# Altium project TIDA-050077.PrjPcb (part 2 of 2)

## Sheet TIDA-050077_HKeeping.SchDoc
size 431 x 279 mm; Date: Not shown in title block; ApprovedBy: Not shown in title block; CheckedBy: Not shown in title block; Author: Not shown in title block; CompanyName: Not shown in title block; Engineer: Not shown in title block; Organization: Not shown in title block; Address1: Not shown in title block; Address2: Not shown in title block; Address3: Not shown in title block; Address4: Not shown in title block; DocumentNumber: 6; Revision: Use project parameter SCH_Rev; SheetNumber: 4; SheetTotal: 5; PageSetup: Record=PageOptions¦CenterHorizontal=True¦CenterVertical=True¦PrintScale=1.00¦XCorrection=1.00¦YCorrection=1.00¦PrintKind=0¦BorderSize=5000000¦LeftOffset=0¦BottomOffset=0¦Orientation=2¦PaperLength=1000¦PaperWidth=1000¦Scale=100¦PaperSource=15¦PrintQuality=600¦MediaType=1¦DitherType=10¦PaperKind=Letter¦PrintScaleMode=1
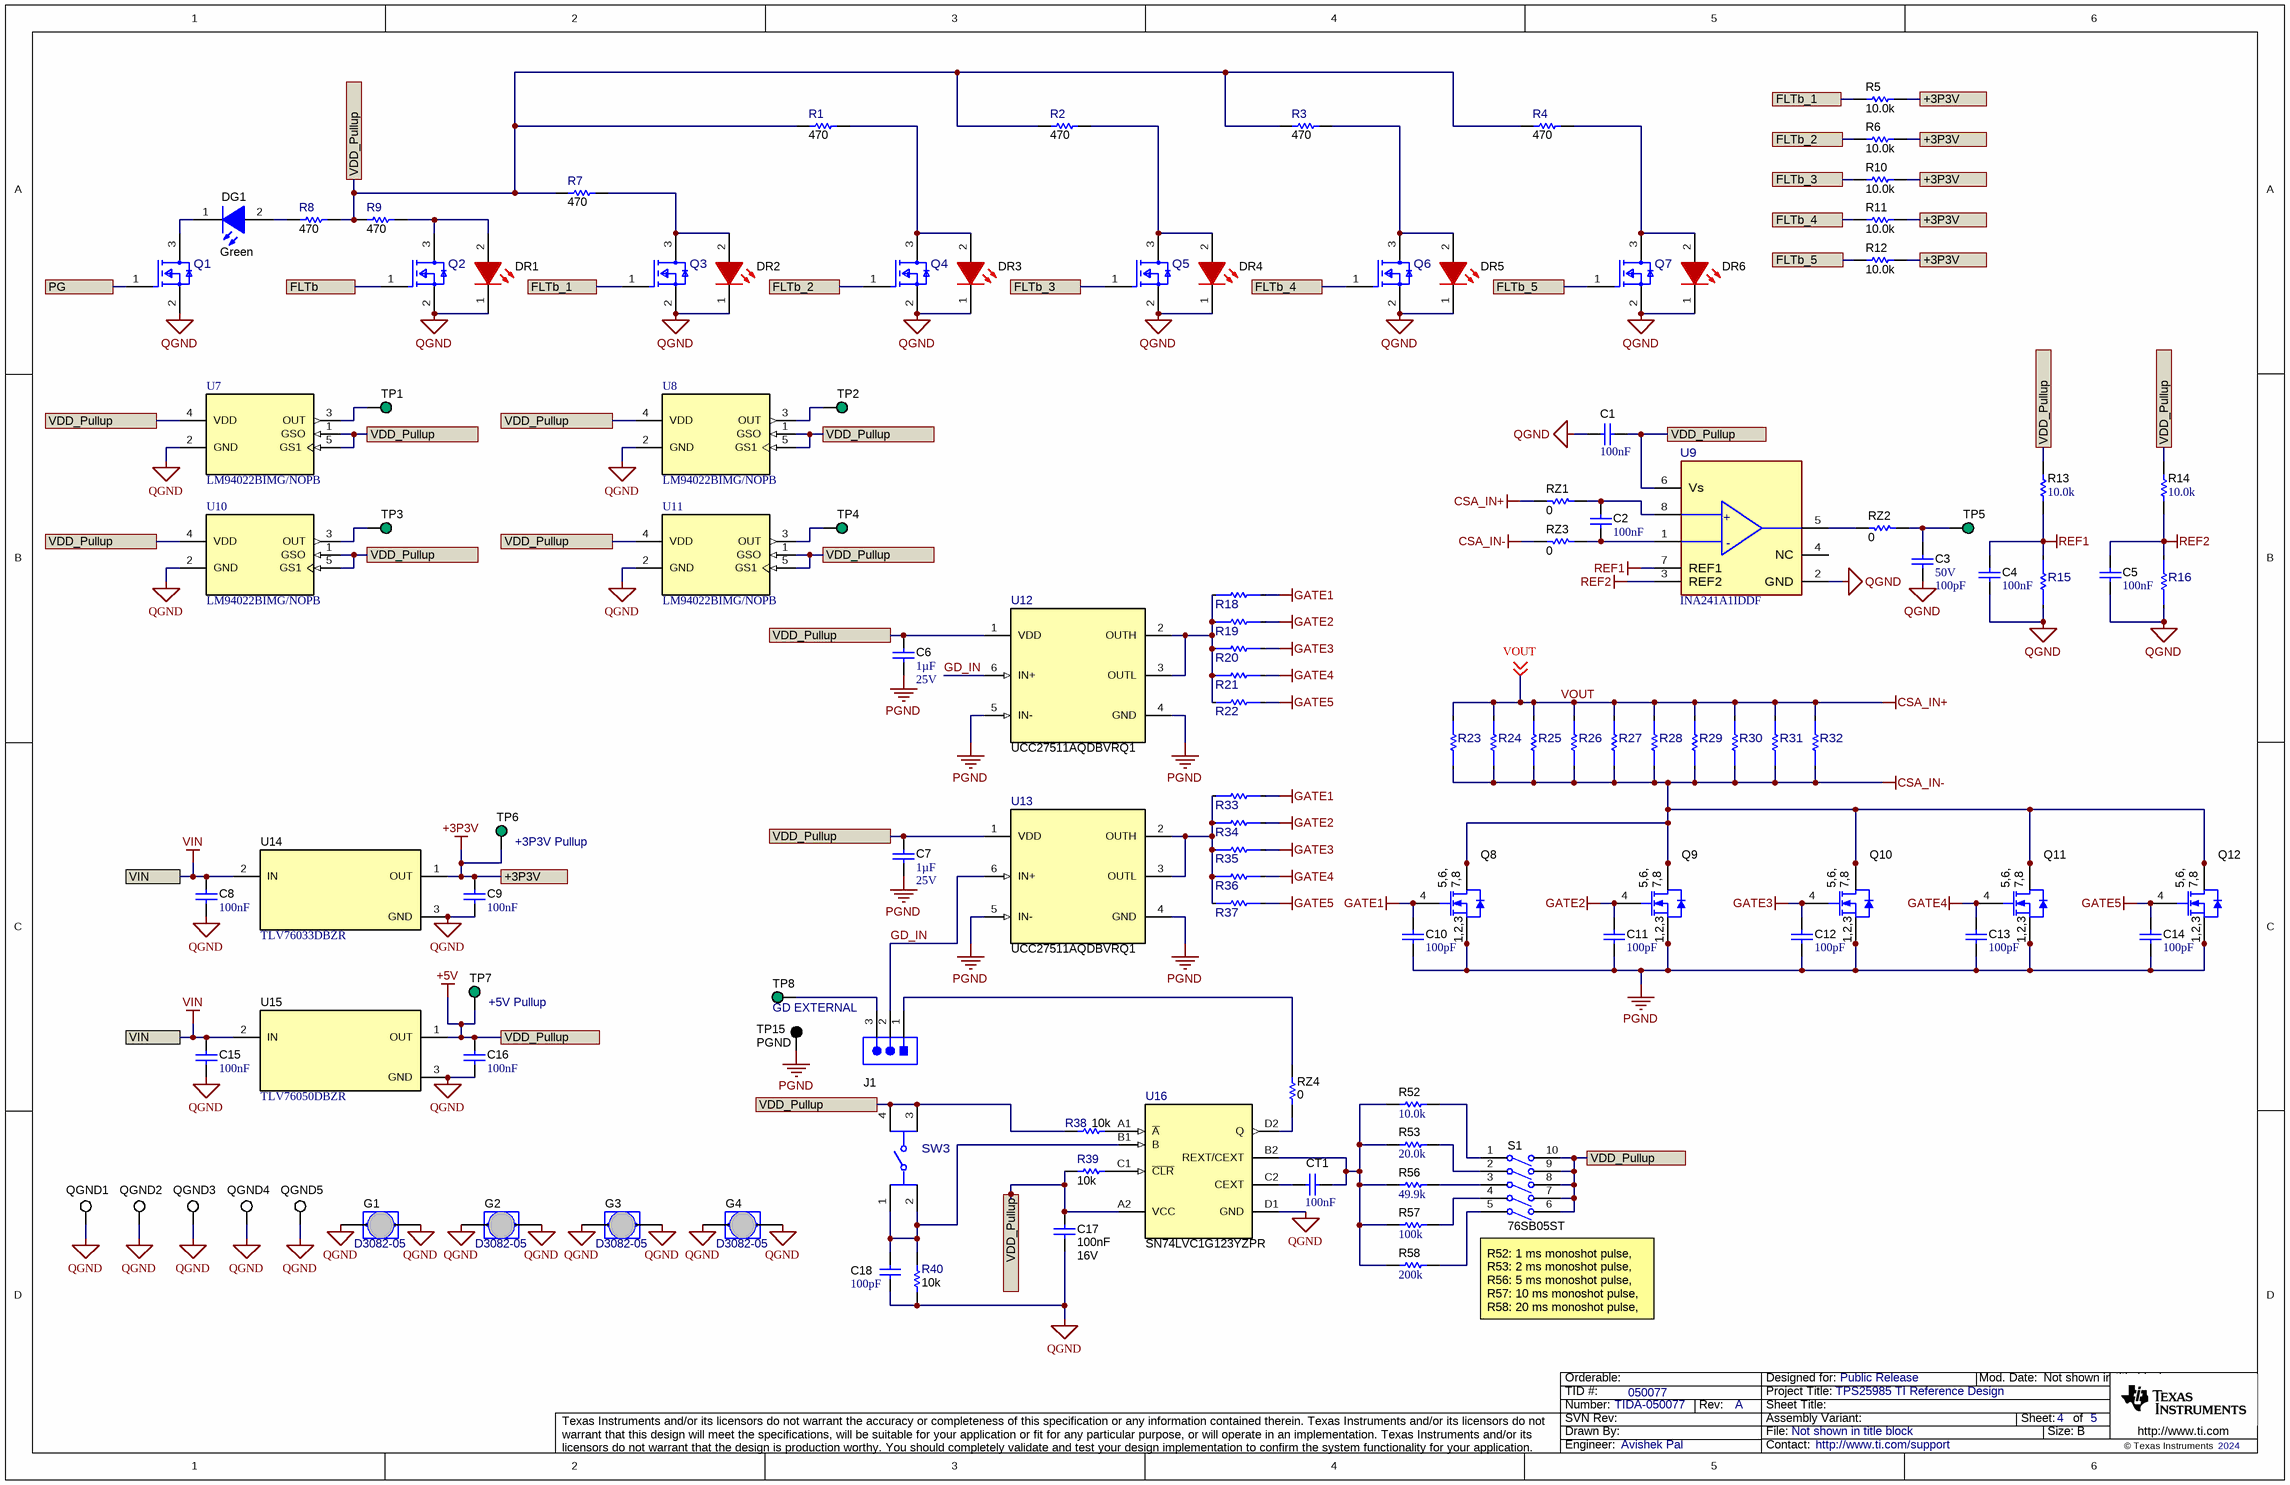
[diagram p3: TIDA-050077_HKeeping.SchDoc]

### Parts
C1  Cap_F: 100nF  [0603]  (hidden comment: 06035C104KAT2A)
C2  Cap_F: 100nF  [0603]  (hidden comment: 06035C104KAT2A)
C3  VDC_V: 50V  ValueDisplayed: 100pF  [0402]  (hidden comment: GRM1555C1H101JA01D)
C4  Cap_F: 100nF  [0603]  (hidden comment: 06035C104KAT2A)
C5  Cap_F: 100nF  [0603]  (hidden comment: 06035C104KAT2A)
C6  Cap_F: 1µF  VDC_V: 25V  [0603]  (hidden comment: GCM188R71E105KA64D)
C7  Cap_F: 1µF  VDC_V: 25V  [0603]  (hidden comment: GCM188R71E105KA64D)
C8  Cap_F: 100nF  [0603]  (hidden comment: 06035C104KAT2A)
C9  Cap_F: 100nF  [0603]  (hidden comment: 06035C104KAT2A)
C10  ValueDisplayed: 100pF  [0603S]  (hidden comment: 885012006057)
C11  ValueDisplayed: 100pF  [0603S]  (hidden comment: 885012006057)
C12  ValueDisplayed: 100pF  [0603S]  (hidden comment: 885012006057)
C13  ValueDisplayed: 100pF  [0603S]  (hidden comment: 885012006057)
C14  ValueDisplayed: 100pF  [0603S]  (hidden comment: 885012006057)
C15  Cap_F: 100nF  [0603]  (hidden comment: 06035C104KAT2A)
C16  Cap_F: 100nF  [0603]  (hidden comment: 06035C104KAT2A)
C17  Cap_F: 100nF  VDC_V: 16V  [0603]  (hidden comment: CL10B104KO8WPNC)
C18  ValueDisplayed: 100pF  [0603]  (hidden comment: 885012006057)
CT1  Cap_F: 100nF  [0603]  (hidden comment: C0603C104K5RACAUTO)
DG1  value Green  [LG_R971_Green]  (hidden comment: LG R971-KN-1)
DR1  LS R976-NR-1  [LS_R976_Red]  (value not drawn)
DR2  LS R976-NR-1  [LS_R976_Red]  (value not drawn)
DR3  LS R976-NR-1  [LS_R976_Red]  (value not drawn)
DR4  LS R976-NR-1  [LS_R976_Red]  (value not drawn)
DR5  LS R976-NR-1  [LS_R976_Red]  (value not drawn)
DR6  LS R976-NR-1  [LS_R976_Red]  (value not drawn)
G1  D3082-05  [Harwin_D3082-05]
G2  D3082-05  [Harwin_D3082-05]
G3  D3082-05  [Harwin_D3082-05]
G4  D3082-05  [Harwin_D3082-05]
J1  Header_3x1_Launchpad  [CONN_PEC03SAAN]  (value not drawn)
Q1  SI2306BDS-T1-GE3  [FP-SI2306BDS-T1-GE3_SOT23-3-MFG]  (value not drawn)
Q2  SI2306BDS-T1-GE3  [FP-SI2306BDS-T1-GE3_SOT23-3-MFG]  (value not drawn)
Q3  SI2306BDS-T1-GE3  [FP-SI2306BDS-T1-GE3_SOT23-3-MFG]  (value not drawn)
Q4  SI2306BDS-T1-GE3  [FP-SI2306BDS-T1-GE3_SOT23-3-MFG]  (value not drawn)
Q5  SI2306BDS-T1-GE3  [FP-SI2306BDS-T1-GE3_SOT23-3-MFG]  (value not drawn)
Q6  SI2306BDS-T1-GE3  [FP-SI2306BDS-T1-GE3_SOT23-3-MFG]  (value not drawn)
Q7  SI2306BDS-T1-GE3  [FP-SI2306BDS-T1-GE3_SOT23-3-MFG]  (value not drawn)
Q8  CSD18510Q5B  [DNK0008A]  (value not drawn)
Q9  CSD18510Q5B  [DNK0008A]  (value not drawn)
Q10  CSD18510Q5B  [DNK0008A]  (value not drawn)
Q11  CSD18510Q5B  [DNK0008A]  (value not drawn)
Q12  CSD18510Q5B  [DNK0008A]  (value not drawn)
QGND1  5016  [Testpoint_Keystone_Compact]  (value not drawn)
QGND2  5016  [Testpoint_Keystone_Compact]  (value not drawn)
QGND3  5016  [Testpoint_Keystone_Compact]  (value not drawn)
QGND4  5016  [Testpoint_Keystone_Compact]  (value not drawn)
QGND5  5016  [Testpoint_Keystone_Compact]  (value not drawn)
R1  ValueDisplayed: 470  [0603]  (hidden comment: RC0603JR-07470RL)
R2  ValueDisplayed: 470  [0603]  (hidden comment: RC0603JR-07470RL)
R3  ValueDisplayed: 470  [0603]  (hidden comment: RC0603JR-07470RL)
R4  ValueDisplayed: 470  [0603]  (hidden comment: RC0603JR-07470RL)
R5  ValueDisplayed: 10.0k  [0402]  (hidden comment: RC0402FR-0710KL)
R6  ValueDisplayed: 10.0k  [0402]  (hidden comment: RC0402FR-0710KL)
R7  ValueDisplayed: 470  [0603]  (hidden comment: RC0603JR-07470RL)
R8  ValueDisplayed: 470  [0603]  (hidden comment: RC0603JR-07470RL)
R9  ValueDisplayed: 470  [0603]  (hidden comment: RC0603JR-07470RL)
R10  ValueDisplayed: 10.0k  [0402]  (hidden comment: RC0402FR-0710KL)
R11  ValueDisplayed: 10.0k  [0402]  (hidden comment: RC0402FR-0710KL)
R12  ValueDisplayed: 10.0k  [0402]  (hidden comment: RC0402FR-0710KL)
R13  ValueDisplayed: 10.0k  [0603]  (hidden comment: RC0603FR-0710KL)
R14  ValueDisplayed: 10.0k  [0603]  (hidden comment: RC0603FR-0710KL)
R15  CR160000F  [FP-CR160000F_0603-MFG]  (value not drawn)
R16  CR160000F  [FP-CR160000F_0603-MFG]  (value not drawn)
R18  RC0603JR-0710RL  [FP-RC0603JR-0710RL_0603-MFG]  (value not drawn)
R19  RC0603JR-0710RL  [FP-RC0603JR-0710RL_0603-MFG]  (value not drawn)
R20  RC0603JR-0710RL  [FP-RC0603JR-0710RL_0603-MFG]  (value not drawn)
R21  RC0603JR-0710RL  [FP-RC0603JR-0710RL_0603-MFG]  (value not drawn)
R22  RC0603JR-0710RL  [FP-RC0603JR-0710RL_0603-MFG]  (value not drawn)
R23  SMW5R51JT  [FP-SMW51R0JT_5329-IPC_C]  (value not drawn)
R24  SMW5R51JT  [FP-SMW51R0JT_5329-IPC_C]  (value not drawn)
R25  SMW5R51JT  [FP-SMW51R0JT_5329-IPC_C]  (value not drawn)
R26  SMW5R51JT  [FP-SMW51R0JT_5329-IPC_C]  (value not drawn)
R27  SMW5R51JT  [FP-SMW51R0JT_5329-IPC_C]  (value not drawn)
R28  CSS2H-3920R-1L00F  [FP-CSS2H-3920R-1L00F_3920-MFG]  (value not drawn)
R29  CSS2H-3920R-1L00F  [FP-CSS2H-3920R-1L00F_3920-MFG]  (value not drawn)
R30  CSS2H-3920R-1L00F  [FP-CSS2H-3920R-1L00F_3920-MFG]  (value not drawn)
R31  CSS2H-3920R-1L00F  [FP-CSS2H-3920R-1L00F_3920-MFG]  (value not drawn)
R32  CSS2H-3920R-1L00F  [FP-CSS2H-3920R-1L00F_3920-MFG]  (value not drawn)
R33  RC0603JR-0710RL  [FP-RC0603JR-0710RL_0603-MFG]  (value not drawn)
R34  RC0603JR-0710RL  [FP-RC0603JR-0710RL_0603-MFG]  (value not drawn)
R35  RC0603JR-0710RL  [FP-RC0603JR-0710RL_0603-MFG]  (value not drawn)
R36  RC0603JR-0710RL  [FP-RC0603JR-0710RL_0603-MFG]  (value not drawn)
R37  RC0603JR-0710RL  [FP-RC0603JR-0710RL_0603-MFG]  (value not drawn)
R38  ValueDisplayed: 10k  [0603]  (hidden comment: RC0603JR-0710KL)
R39  ValueDisplayed: 10k  [0603]  (hidden comment: RC0603JR-0710KL)
R40  ValueDisplayed: 10k  [0603]  (hidden comment: RC0603JR-0710KL)
R52  ValueDisplayed: 10.0k  [0603]  (hidden comment: CRCW060310K0FKEA)
R53  ValueDisplayed: 20.0k  [0603]  (hidden comment: CRCW060320K0FKEA)
R56  ValueDisplayed: 49.9k  [0603]  (hidden comment: CRCW060349K9FKEA)
R57  ValueDisplayed: 100k  [0603]  (hidden comment: CRCW0603100KFKEA)
R58  ValueDisplayed: 200k  [0603]  (hidden comment: CRCW0603200KFKEA)
RZ1  ValueDisplayed: 0  [0402]  (hidden comment: CRCW04020000Z0ED)
RZ2  ValueDisplayed: 0  [0402]  (hidden comment: CRCW04020000Z0ED)
RZ3  ValueDisplayed: 0  [0402]  (hidden comment: CRCW04020000Z0ED)
RZ4  ValueDisplayed: 0  [0402]  (hidden comment: CRCW04020000Z0ED)
S1  76SB05ST  [SW_76SB05]
SW3  PTS830GM140SMTRLFS  [FP-PTS830GM140SMTRLFS_SMT_3MM05_2MM6-MFG]  (value not drawn)
TP1  (no value)  [Keystone5126]
TP2  (no value)  [Keystone5126]
TP3  (no value)  [Keystone5126]
TP4  (no value)  [Keystone5126]
TP5  (no value)  [Keystone5126]
TP6  +3P3V Pullup  [Keystone5126]
TP7  +5V Pullup  [Keystone5126]
TP8  GD EXTERNAL  [Keystone5126]
TP15  PGND  [Keystone5011]
U7  LM94022BIMG/NOPB  [DCK0005A_N]
U8  LM94022BIMG/NOPB  [DCK0005A_N]
U9  INA241A1IDDF  [DDF0008A-MFG]
U10  LM94022BIMG/NOPB  [DCK0005A_N]
U11  LM94022BIMG/NOPB  [DCK0005A_N]
U12  UCC27511AQDBVRQ1  [DBV0006A_N]
U13  UCC27511AQDBVRQ1  [DBV0006A_N]
U14  TLV76033DBZR  [DBZ0003A_N]
U15  TLV76050DBZR  [DBZ0003A_N]
U16  SN74LVC1G123YZPR  [YZP0008ADAD]

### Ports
+3P3V, FLTb, FLTb_1, FLTb_2, FLTb_3, FLTb_4, FLTb_5, PG, VDD_Pullup, VIN

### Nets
+3P3V: C9.1 R5.1 R6.1 R10.1 R11.1 R12.1 TP6.1 U14.1(OUT) ; port +3P3V
+5V: C1.2 C6.1 C7.1 C16.1 C17.1 R1.1 R2.1 R3.1 R4.1 R7.1 R8.2 R9.1 R13.2 R14.2 R38.2 R39.2 S1.6 S1.7 S1.8 S1.9 S1.10 SW3.3 SW3.4 TP7.1 U7.1(GSO) U7.4(VDD) U7.5(GS1) U8.1(GSO) U8.4(VDD) U8.5(GS1) U9.6(Vs) U10.1(GSO) U10.4(VDD) U10.5(GS1) U11.1(GSO) U11.4(VDD) U11.5(GS1) U12.1(VDD) U13.1(VDD) U15.1(OUT) U16.A2(VCC) ; port VDD_Pullup
CSA_IN-: Q8.5(D) Q8.6(D) Q8.7(D) Q8.8(D) Q8.9(D) Q9.5(D) Q9.6(D) Q9.7(D) Q9.8(D) Q9.9(D) Q10.5(D) Q10.6(D) Q10.7(D) Q10.8(D) Q10.9(D) Q11.5(D) Q11.6(D) Q11.7(D) Q11.8(D) Q11.9(D) Q12.5(D) Q12.6(D) Q12.7(D) Q12.8(D) Q12.9(D) R23.1 R24.1 R25.1 R26.1 R27.1 R28.1 R29.1 R30.1 R31.1 R32.1 RZ3.2
GATE1: C10.2 Q8.4(G) R18.2 R33.2
GATE2: C11.2 Q9.4(G) R19.2 R34.2
GATE3: C12.2 Q10.4(G) R20.2 R35.2
GATE4: C13.2 Q11.4(G) R21.2 R36.2
GATE5: C14.2 Q12.4(G) R22.2 R37.2
PGND: C6.2 C7.2 C10.1 C11.1 C12.1 C13.1 C14.1 Q8.1(S) Q8.2(S) Q8.3(S) Q9.1(S) Q9.2(S) Q9.3(S) Q10.1(S) Q10.2(S) Q10.3(S) Q11.1(S) Q11.2(S) Q11.3(S) Q12.1(S) Q12.2(S) Q12.3(S) TP15.1 U12.4(GND) U12.5(IN-) U13.4(GND) U13.5(IN-)
QGND: C1.1 C3.2 C4.1 C5.1 C8.2 C9.2 C15.2 C16.2 C17.2 C18.1 DR1.1(K) DR2.1(K) DR3.1(K) DR4.1(K) DR5.1(K) DR6.1(K) G1.1 G1.2 G2.1 G2.2 G3.1 G3.2 G4.1 G4.2 Q1.2(S) Q2.2(S) Q3.2(S) Q4.2(S) Q5.2(S) Q6.2(S) Q7.2(S) QGND1.1 QGND2.1 QGND3.1 QGND4.1 QGND5.1 R15.1 R16.1 R40.2 U7.2(GND) U8.2(GND) U9.2(GND) U10.2(GND) U11.2(GND) U14.3(GND) U15.3(GND) U16.D1(GND)
REF1: C4.2 R13.1 R15.2 U9.7(REF1)
REF2: C5.2 R14.1 R16.2 U9.3(REF2)
VIN: C8.1 C15.1 U14.2(IN) U15.2(IN) ; port VIN
VOUT: R23.2 R24.2 R25.2 R26.2 R27.2 R28.2 R29.2 R30.2 R31.2 R32.2 RZ1.2 ; off-sheet VOUT  [also labelled CSA_IN+]
GD_IN: J1.2 U12.6(IN+) U13.6(IN+)
NetC2_1: C2.1 RZ3.1 U9.1(IN-)
NetC2_2: C2.2 RZ1.1 U9.8(IN+)
NetC3_1: C3.1 RZ2.1 TP5.1
NetC18_2: C18.2 R40.1 SW3.1 SW3.2 U16.B1(B)
NetCT1_1: CT1.1 U16.C2(CEXT)
NetCT1_2: CT1.2 R52.1 R53.1 R56.1 R57.1 R58.1 U16.B2(REXT/CEXT)
NetDG1_1: DG1.1(K) Q1.3(D)
NetDG1_2: DG1.2(A) R8.1
NetDR1_2: DR1.2(A) Q2.3(D) R9.2
NetDR2_2: DR2.2(A) Q3.3(D) R7.2
NetDR3_2: DR3.2(A) Q4.3(D) R1.2
NetDR4_2: DR4.2(A) Q5.3(D) R2.2
NetDR5_2: DR5.2(A) Q6.3(D) R3.2
NetDR6_2: DR6.2(A) Q7.3(D) R4.2
NetJ1_1: J1.1 RZ4.2
NetJ1_3: J1.3 TP8.1
NetQ1_1: Q1.1(G) ; port PG
NetQ2_1: Q2.1(G) ; port FLTb
NetQ3_1: Q3.1(G) R5.2 ; port FLTb_1
NetQ4_1: Q4.1(G) R6.2 ; port FLTb_2
NetQ5_1: Q5.1(G) R10.2 ; port FLTb_3
NetQ6_1: Q6.1(G) R11.2 ; port FLTb_4
NetQ7_1: Q7.1(G) R12.2 ; port FLTb_5
NetR18_1: R18.1 R19.1 R20.1 R21.1 R22.1 U12.2(OUTH) U12.3(OUTL)
NetR33_1: R33.1 R34.1 R35.1 R36.1 R37.1 U13.2(OUTH) U13.3(OUTL)
NetR38_1: R38.1 U16.A1(~{A})
NetR39_1: R39.1 U16.C1(~{CLR})
NetR52_2: R52.2 S1.1
NetR53_2: R53.2 S1.2
NetR56_2: R56.2 S1.3
NetR57_2: R57.2 S1.4
NetR58_2: R58.2 S1.5
NetRZ2_2: RZ2.2 U9.5(OUT)
NetRZ4_1: RZ4.1 U16.D2(Q)
NetTP1_1: TP1.1 U7.3(OUT)
NetTP2_1: TP2.1 U8.3(OUT)
NetTP3_1: TP3.1 U10.3(OUT)
NetTP4_1: TP4.1 U11.3(OUT)

Not connected (* = marked no-connect by the designer): U9 4(NC)

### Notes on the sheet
- (near S1) R52: 1 ms monoshot pulse,
  R53: 2 ms monoshot pulse,
  R56: 5 ms monoshot pulse,
  R57: 10 ms monoshot pulse,
  R58: 20 ms monoshot pulse,

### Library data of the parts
C1 C2 C4 C5 C8 C9 C15 C16 = CMP-0006802-4: CAP, CERM, 0.1 uF, 50 V, +/- 10%, X7R, 0603; Manufacturer: AVX; TaMin_C: -55°C; Polarized: N; SizeAreaWB_mm2: 4.68; Value1: Unknown; U/M: EA; Value: 0.1uF; TaMax_C: 125°C; SizeZ_mm: 1; SizeX_mm: 1.6; SizeY_mm: 0.8; Value2: 50V; SizeArea_mm2: 1.28; AEC Category: Q200
C3 = CMP-0006410-2: CAP, CERM, 100 pF, 50 V, +/- 5%, C0G/NP0, 0402; Manufacturer: MuRata; TaMin_C: -55°C; Polarized: N; SizeAreaWB_mm2: 3; Value1: Unknown; U/M: EA; Value: 100pF; TaMax_C: 125°C; SizeZ_mm: 0.6; SizeX_mm: 1; SizeY_mm: 0.5; AEC Category: Q200
C6 C7 = CMP-0007139-4: CAP, CERM, 1 uF, 25 V, +/- 10%, X7R, AEC-Q200 Grade 1, 0603; Manufacturer: MuRata; TaMin_C: -55°C; Polarized: N; SizeAreaWB_mm2: 4.68; Value1: Unknown; U/M: EA; Value: 1uF; TaMax_C: 125°C; SizeZ_mm: 1; SizeX_mm: 1.6; SizeY_mm: 0.8; SizeArea_mm2: 1.28; AEC Qualified: Y; AEC Category: Q200
C10-C14 = CMP-0006822-4: CAP, CERM, 100 pF, 50 V, +/- 5%, C0G/NP0, 0603; Manufacturer: Wurth Elektronik; TaMin_C: -55°C; Polarized: N; SizeAreaWB_mm2: 4.68; Value1: Unknown; U/M: EA; Value: 100pF; TaMax_C: 125°C; SizeZ_mm: 1; SizeX_mm: 1.6; SizeY_mm: 0.8; Cap_Case: 0603; Value2: 50V; SizeArea_mm2: 1.28; CompType: Capacitor; AEC Category: Q200
C17 = CMP-0085536-1: CAP, CERM, 0.1 µF, 16 V,+/- 10%, X7R, 0603; Manufacturer: Samsung Electro-Mechanics; SizeArea_mm2: 1.28; SizeY_mm: 0.8; AEC Category: Q200; Polarized: N; AEC Qualified: Y; ValueDisplayed: 0.1µF; TaMax_C: 125°C; SizeZ_mm: 1; U/M: EA; SizeX_mm: 1.6; Value: 0.1uF; TaMin_C: -55°C; SizeAreaWB_mm2: 4.68
C18 = CMP-0006822-4: CAP, CERM, 100 pF, 50 V, +/- 5%, C0G/NP0, 0603; Manufacturer: Wurth Elektronik; TaMin_C: -55°C; Polarized: N; SizeAreaWB_mm2: 4.68; Value1: Unknown; U/M: EA; Value: 100pF; TaMax_C: 125°C; SizeZ_mm: 1; SizeX_mm: 1.6; SizeY_mm: 0.8; Value2: 50V; SizeArea_mm2: 1.28; CompType: Capacitor; AEC Category: Q200
CT1 = CMP-0079602-1: CAP, CERM, 0.1 µF, 50 V,+/- 10%, X7R, AEC-Q200 Grade 1, 0603; Manufacturer: Kemet; TaMin_C: -55°C; Polarized: N; SizeAreaWB_mm2: 4.68; U/M: EA; Value: 0.1uF; TaMax_C: 125°C; SizeZ_mm: 1; SizeX_mm: 1.6; SizeY_mm: 0.8; Value2: 50V; SizeArea_mm2: 1.28; AEC Qualified: Y; AEC Category: Q200; ValueDisplayed: 0.1µF
DG1 = CMP-0002980-2: LED, Green, SMD; Manufacturer: OSRAM; Io_A: 20mA; Vr_V: 12V; Tjmax_C: 95°C; Value1: W; U/M: EA; Angle: 160; Ir_A: 100µA; Vf_V: 2.2V
DR1-DR6 = CMP-0082438-1: LED, Red, SMD; Manufacturer: OSRAM; Tjmax_C: 95°C; SizeAreaWB_mm2: 6.75; Vr_V: 12V; Angle: 160; SizeArea_mm2: 2.5; Ir_A: 10nA; SizeZ_mm: 0.9; Io_A: 20mA; Vf_V: 2V; SizeY_mm: 1.25; Value1: W; SizeX_mm: 2
G1-G4 = CMP-0075110-1: 1mm Uninsulated Shorting Plug, 10.16mm spacing, TH; Manufacturer: Harwin; CNHeader: False; Green_Lifecycle: Active; Green_REACh: Passed; CompType: Jumper Wire
J1 = CMP-0002338-1: Header, 100mil, 3x1, Tin, TH; PartNumber: PEC03SAAN; Manufacturer: Sullins Connector Solutions; Cert_UL: Y; CNHeader: TRUE; CT: FALSE; Current_A: 3A; Gender: Male; Green_Lifecycle: Not Set; Green_REACh: Incomplete; Pitch_mm: 2.54; Row_Count: 1; Shrouded: N; Voltage_V: 1.8kV
Q1-Q7 = CMP-0095692-1: N-Channel 30 V 3.16A (Ta) 750mW (Ta) Surface Mount SOT-23-3 (TO-236); Manufacturer: Vishay Siliconix; Threshold Vgs Min: 1V; Pulse Drain Current: 20A; IdsMax_A: 4A; Typ Forward Diode Voltage: 0.8V; Rdson45_ohm: 38m; AEC Qualified: No; TJmax_C: +150°C; SizeZ_mm: 1.12mm; Input Capacitace At Vds: 305pF @ 15V; Power_W: 1.25W; Reverse Recovery Time: 14ns; ChMode: False; Turn On Delay Time: 7ns; Threshold Vgs Max: 3V; Reverse Recovery Charge: 6nC; Vgs_V: 20V; Transconductance: 7S; Drain To Source Breakdown Voltage: 30V; Number Of N Channels: 1; VdsMax_V: 1.2V; Rthja Max: 130°C/W; Standoff Height: 0.01mm; QgTyp_nC: 3nC @ 5V
Q8-Q12 = CMP-0077216-2: MOSFET, N-CH, 40 V, 42 A, DNK0008A (VSON-CLIP-8); Manufacturer: Texas Instruments; Alternate Manufacturer: None; Value2: 118 nC; Value1: 0.0016 ohm; SizeX_mm: 6.0; SizeY_mm: 5.0; SizeZ_mm: 1.0; AEC Qualified: N; Value: 40V; SizeArea_mm2: 30.0; AEC Category: Q101; SizeAreaWB_mm2: 56.0; U/M: EA; Vgs_V: 20V; Rdson45_ohm: 1.6m; IdsMax_A: 42A; QgTyp_nC: 118.0
QGND1-QGND5 = CMP-0055153-1: Test Point, Compact, SMT; Manufacturer: Keystone; CNHeader: FALSE; CT: TRUE; Green_Lifecycle: Active; Green_REACh: Passed
R1-R4 R7-R9 = CMP-0025924-5: RES, 470, 5%, 0.1 W, 0603; Manufacturer: Yageo; Power_W: 100mW; TempCo: 100 ppm/C; Value_Code: 470R; Value: 470; EIA_Code: E24; SizeX_mm: 1.6; SizeY_mm: 0.8; SizeZ_mm: 1; Value2: 0.1W; SizeArea_mm2: 1.28; AEC Qualified: N; VDC_V: 75V; AEC Category: Q200; SizeAreaWB_mm2: 4.68
R5 R6 R10-R12 = CMP-0078669-1: RES, 10.0 k, 1%, 0.063 W, 0402; Manufacturer: Yageo America; Power_W: 63mW; Green_Lifecycle: Active; TempCo: 100 ppm/C; Value_Code: 10k0; Green_REACh: Passed; Value: 10.0k; EIA_Code: E96; Res_ohm: 10k; SizeX_mm: 1; SizeY_mm: 0.5; SizeZ_mm: 0.6; Value2: 0.063W; AEC Qualified: N; AEC Category: Q200
R13 R14 = CMP-0022746-5: RES, 10.0 k, 1%, 0.1 W, 0603; Manufacturer: Yageo; Power_W: 100mW; TempCo: 100 ppm/C; Value_Code: 10k0; Value: 10.0k; EIA_Code: E96; Res_ohm: 10k; SizeX_mm: 1.6; SizeY_mm: 0.8; SizeZ_mm: 1; Value2: 0.1W; SizeArea_mm2: 1.28; AEC Qualified: N; VDC_V: 75V; AEC Category: Q200; SizeAreaWB_mm2: 4.68
R15 R16 = CMP-0097819-1: 0 Ohms ±1% Chip Resistor 0603 (1608 Metric) Thick Film; Manufacturer: Meritek Electronics; SizeZ_mm: 0.55mm; AEC Qualified: No; VDC_V: 75V; Value: 0; Power_W: 100mW; Max Current: 2A
R18-R22 R33-R37 = CMP-0095691-1: Res General Purpose Thick Film 0603 10 Ohm 5% 1/10W ±200ppm/°C Molded SMD Paper T/R; Manufacturer: Yageo; Res_ohm: 10; AEC Qualified: No; Value: 10; SizeZ_mm: 0.55mm; Power_W: 100mW; VDC_V: 75V
R23-R27 = CMP-0095896-1: 510 mOhms ±5% 5W Chip Resistor 5329 (13573 Metric), J-Lead Flame Retardant Coating, Safety Wirewound; Manufacturer: TE Connectivity; Value: 1; VDC_V: 500V; TempCo: 200ppm/°C; AEC Qualified: No; Res_ohm: 0.51; SizeZ_mm: 7.1mm
R28-R32 = CMP-0091489-1: 1 mOhms ±1% 8W Chip Resistor 3920 (1052 Metric) Current Sense, Moisture Resistant Metal Element; Manufacturer: Bourns; Value: 1m; AEC Grade: Grade 0; AEC Qualified: Yes; TempCo: 100ppm/°C; Standoff Height: 0.3mm; SizeZ_mm: 1.02mm
R38-R40 = CMP-0025886-5: RES, 10 k, 5%, 0.1 W, 0603; Manufacturer: Yageo; Power_W: 100mW; TempCo: 100 ppm/C; Value_Code: 10k0; Value: 10k; EIA_Code: E24; SizeX_mm: 1.6; SizeY_mm: 0.8; SizeZ_mm: 1; Value2: 0.1W; SizeArea_mm2: 1.28; AEC Qualified: N; VDC_V: 75V; AEC Category: Q200; SizeAreaWB_mm2: 4.68
R52 = CMP-0021998-2: RES, 10.0 k, 1%, 0.1 W, 0603; Manufacturer: Vishay-Dale; Power_W: 100mW; TempCo: 100 ppm/C; Value_Code: 10k0; U/M: EA; Value: 10.0k; EIA_Code: E96; Res_ohm: 10k; SizeX_mm: 1.6; SizeY_mm: 0.8; SizeZ_mm: 1; Value2: 0.1W; SizeArea_mm2: 1.28; VDC_V: 75V; AEC Category: Q200
R53 = CMP-0022204-1: RES, 20.0 k, 1%, 0.1 W, 0603; Manufacturer: Vishay-Dale; Power_W: 100mW; TempCo: 100 ppm/C; Value_Code: 20k0; U/M: EA; Value: 20.0k; EIA_Code: E96; Res_ohm: 20k; SizeX_mm: 1.6; SizeY_mm: 0.8; SizeZ_mm: 1; Value2: 0.1W; SizeArea_mm2: 1.28; VDC_V: 75V; AEC Category: Q200
R56 = CMP-0022447-1: RES, 49.9 k, 1%, 0.1 W, 0603; Manufacturer: Vishay-Dale; Power_W: 100mW; TempCo: 100 ppm/C; Value_Code: 49k9; U/M: EA; Value: 49.9k; EIA_Code: E96; SizeX_mm: 1.6; SizeY_mm: 0.8; SizeZ_mm: 1; Value2: 0.1W; SizeArea_mm2: 1.28; VDC_V: 75V; AEC Category: Q200
R57 = CMP-0021990-4: RES, 100 k, 1%, 0.1 W, AEC-Q200 Grade 0, 0603; Manufacturer: Vishay-Dale; Power_W: 100mW; TempCo: 100 ppm/C; Value: 100k; EIA_Code: E96; SizeX_mm: 1.6; SizeY_mm: 0.8; SizeZ_mm: 1; Value2: 0.1W; SizeArea_mm2: 1.28; AEC Qualified: Y; VDC_V: 75V; AEC Category: Q200; AEC Grade: 0
R58 = CMP-0022200-1: RES, 200 k, 1%, 0.1 W, 0603; Manufacturer: Vishay-Dale; Power_W: 100mW; TempCo: 100 ppm/C; U/M: EA; Value: 200k; EIA_Code: E96; SizeX_mm: 1.6; SizeY_mm: 0.8; SizeZ_mm: 1; Value2: 0.1W; SizeArea_mm2: 1.28; VDC_V: 75V; AEC Category: Q200
RZ1-RZ4 = CMP-0026822-3: RES, 0, 5%, 0.063 W, AEC-Q200 Grade 0, 0402; Manufacturer: Vishay-Dale; Power_W: 63mW; TempCo: 200 ppm/C; Value_Code: 0000; Value: 0; EIA_Code: E24; SizeX_mm: 1; SizeY_mm: 0.5; SizeZ_mm: 0.6; Value2: 0.063W; AEC Qualified: Y; VDC_V: 50V; AEC Category: Q200
S1 = CMP-0002222-1: Switch, SPST 5Pos, Rocker, TH; Manufacturer: Grayhill; CurrentRating_mA: 150A; PositionCount: 5; VDC_V: 30V; SwitchFunction: Off-On
SW3 = CMP-0087766-1: Tactile Switch SPST-NO Top Actuated Surface Mount; Manufacturer: C&K Components; VDC_V: 12V; Circuit: SPST; SizeZ_mm: 1.5mm
TP1-TP8 = CMP-0055158-1: Test Point, Multipurpose, Green, TH; Manufacturer: Keystone; CNHeader: FALSE; Green_Lifecycle: Active; Green_REACh: Passed; ContactFinish: Silver; CT: TRUE
TP15 = CMP-0055148-1: Test Point, Multipurpose, Black, TH; Manufacturer: Keystone; PartNumber: 5011; CNHeader: FALSE; Green_Lifecycle: Active; Green_REACh: Passed; ContactFinish: Silver; CT: TRUE
U7 U8 U10 U11 = CMP-0073328-2: 1.5V, Multi-Gain Analog Temperature Sensor with Class-AB Output, 5-pin SC-70, Pb-Free; Manufacturer: Texas Instruments; CompType: Temp Sensor IC; PowerWise: Y; PackageTopMarking: 22B*XTT; AEC Category: Q200; AEC Qualified: N; SizeAreaWB_mm2: 9.3; SizeArea_mm2: 4.2; SizeX_mm: 2.1; SizeY_mm: 2.0; SizeZ_mm: 1.1
U9 = CMP-0093647-2: -4-V to 110V, Bidirectional, Ultra-Precise Current Sense Amplifier With Enhanced PWM Rejection; Manufacturer: Texas Instruments; AEC Category: Q200; CompType: IC; Voltage Gain: 0.01V/mV; Input Bias Current: 40uA; AEC Qualified: No; Standoff Height: 0mm; Response Time: 1.5us; TaMax_C: +125°C; Bandwidth: 1MHz; TaMin_C: -40°C; Input Offset Voltage: 0.002mV; Nominal Supply Current: 2.5mA; SizeZ_mm: 1.1mm; Min Supply Voltage: 2.7V; TJmax_C: +150°C; Number Of Channels: 1; Max Supply Voltage: 20V
U12 U13 = CMP-0077683-1: Single-Channel High-Speed Low-Side Gate Driver with 5V Negative Input Voltage Handling Ability, DBV0006A (SOT-23-6); Alternate Manufacturer: Texas Instruments; SizeAreaWB_mm2: 14.82; SizeZ_mm: 1.45; SizeX_mm: 2.8; SizeY_mm: 2.9; SizeArea_mm2: 8.12; CompType: IC; AEC Qualified: Y; AEC Category: Q200
U14 = CMP-0074893-1: 100-mA, 30-V, Fixed-Output, Linear-Voltage Regulator, DBZ0003A (SOT-23-3); Alternate PartNumber: TLV76033DBZT; Alternate Manufacturer: Texas Instruments; SizeAreaWB_mm2: 14.0; SizeZ_mm: 1.12; SizeX_mm: 2.5; SizeY_mm: 3.0; SizeArea_mm2: 7.5; CompType: IC; AEC Qualified: N; AEC Category: Q200
U15 = CMP-0074892-1: 100-mA, 30-V, Fixed-Output, Linear-Voltage Regulator, DBZ0003A (SOT-23-3); Alternate PartNumber: TLV76050DBZT; Alternate Manufacturer: Texas Instruments; SizeAreaWB_mm2: 14.0; SizeZ_mm: 1.12; SizeX_mm: 2.5; SizeY_mm: 3.0; SizeArea_mm2: 7.5; CompType: IC; AEC Qualified: N; AEC Category: Q200
U16 = CMP-0050969-2: Single Retriggerable Monostable Multivibrator with Schmitt-Trigger Inputs, YZP0008ADAD, LARGE T&R; Manufacturer: Texas Instruments; Output Type: CMOS; Bits(#): 1; Input Type: CMOS/TTL; Technology Family: LVC; Schmitt Trigger: Yes; 3-State Output: No; VCC(Max)(V): 5.5; Rating: Catalog; Output Drive (IOL/IOH)(Max)(mA): 32/-32; ICC @ Nom Voltage(Max)(mA): 0.02; VCC(Min)(V): 1.65; F @ Nom Voltage(Max)(Mhz): 150; Logic: True; Voltage(Nom)(V): 1.8,2.5,3.3,5; tpd @ Nom Voltage(Max)(ns): 34,11,8,5.5

## Sheet TIDA-050077_Hardware.SchDoc
size 431 x 279 mm; Date: Not shown in title block; ApprovedBy: Not shown in title block; CheckedBy: Not shown in title block; Author: Not shown in title block; CompanyName: Not shown in title block; Engineer: Not shown in title block; Organization: Not shown in title block; Address1: Not shown in title block; Address2: Not shown in title block; Address3: Not shown in title block; Address4: Not shown in title block; DocumentNumber: 7; Revision: Use project parameter SCH_Rev; SheetNumber: 5; SheetTotal: 5; PageSetup: Record=PageOptions¦CenterHorizontal=True¦CenterVertical=True¦PrintScale=1.00¦XCorrection=1.00¦YCorrection=1.00¦PrintKind=0¦BorderSize=5000000¦LeftOffset=0¦BottomOffset=0¦Orientation=2¦PaperLength=1000¦PaperWidth=1000¦Scale=100¦PaperSource=15¦PrintQuality=600¦MediaType=1¦DitherType=10¦PaperKind=Letter¦PrintScaleMode=1
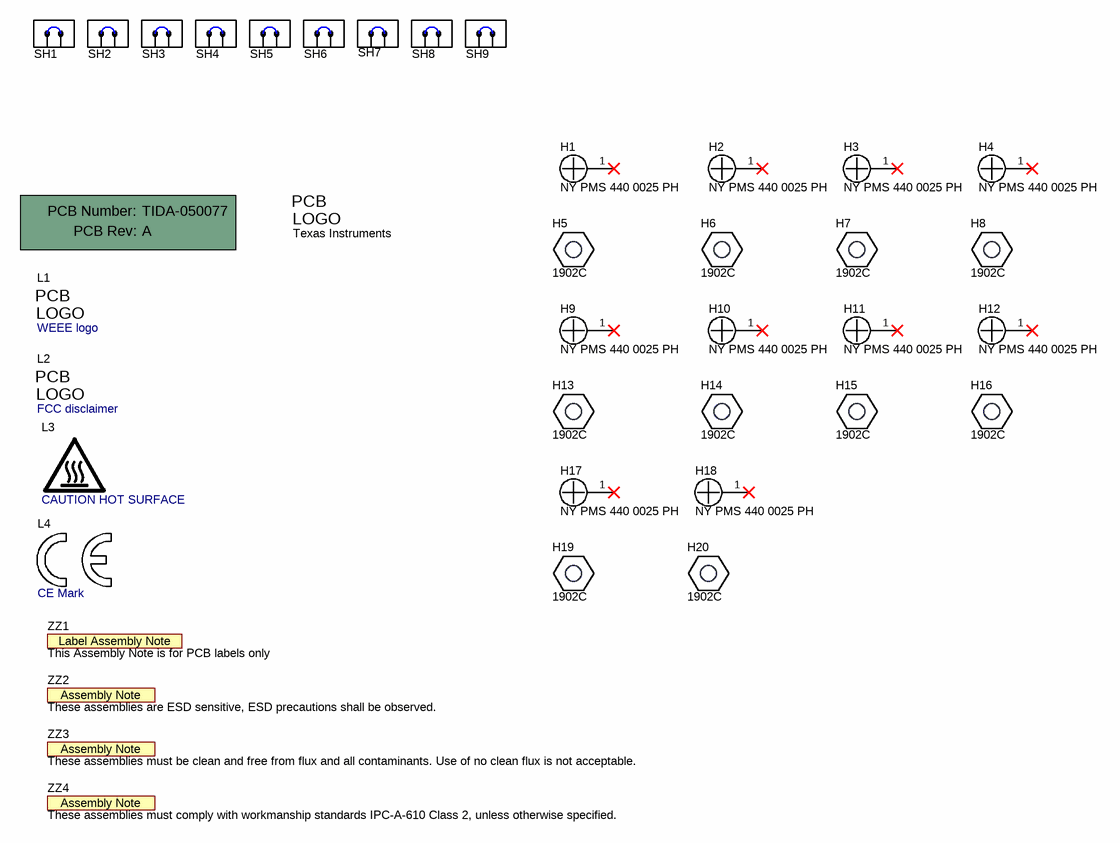
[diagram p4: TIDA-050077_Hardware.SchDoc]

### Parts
!PCB1  Printed Circuit Board  (value not drawn)  (mechanical)
H1  NY PMS 440 0025 PH  [NY PMS 440 0025 PH]
H2  NY PMS 440 0025 PH  [NY PMS 440 0025 PH]
H3  NY PMS 440 0025 PH  [NY PMS 440 0025 PH]
H4  NY PMS 440 0025 PH  [NY PMS 440 0025 PH]
H5  1902C  [Keystone_1902C]
H6  1902C  [Keystone_1902C]
H7  1902C  [Keystone_1902C]
H8  1902C  [Keystone_1902C]
H9  NY PMS 440 0025 PH  [NY PMS 440 0025 PH]
H10  NY PMS 440 0025 PH  [NY PMS 440 0025 PH]
H11  NY PMS 440 0025 PH  [NY PMS 440 0025 PH]
H12  NY PMS 440 0025 PH  [NY PMS 440 0025 PH]
H13  1902C  [Keystone_1902C]
H14  1902C  [Keystone_1902C]
H15  1902C  [Keystone_1902C]
H16  1902C  [Keystone_1902C]
H17  NY PMS 440 0025 PH  [NY PMS 440 0025 PH]
H18  NY PMS 440 0025 PH  [NY PMS 440 0025 PH]
H19  1902C  [Keystone_1902C]
H20  1902C  [Keystone_1902C]
L1  WEEE logo  [WEEE_Minimum]  (no BOM)
L2  FCC disclaimer  [FCC_disclaimer]  (no BOM)
L3  CAUTION HOT SURFACE  [IEC_HotSurface_Small]  (no BOM)
L4  CE Mark  [CE_Mark_5mm]  (no BOM)
Logo1  Texas Instruments  [TI_Stacked_Overlay_Small]  (no BOM)
SH1  60900213621  [Wurth_60900213621]  (value not drawn)
SH2  60900213621  [Wurth_60900213621]  (value not drawn)
SH3  60900213621  [Wurth_60900213621]  (value not drawn)
SH4  60900213621  [Wurth_60900213621]  (value not drawn)
SH5  60900213621  [Wurth_60900213621]  (value not drawn)
SH6  60900213621  [Wurth_60900213621]  (value not drawn)
SH7  60900213621  [Wurth_60900213621]  (value not drawn)
SH8  60900213621  [Wurth_60900213621]  (value not drawn)
SH9  60900213621  [Wurth_60900213621]  (value not drawn)
ZZ1  This Assembly Note is for PCB labels only  [AssemblyNoteLabel]  (no BOM)
ZZ2  These assemblies are ESD sensitive, ESD precautions shall be observed.  [AssemblyNote]  (no BOM)
ZZ3  These assemblies must be clean and free from flux and all contaminants. Use of no clean flux is not acceptable.  [AssemblyNote]  (no BOM)
ZZ4  These assemblies must comply with workmanship standards IPC-A-610 Class 2, unless otherwise specified.  [AssemblyNote]  (no BOM)

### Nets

Not connected (* = marked no-connect by the designer): H1 1*; H2 1*; H3 1*; H4 1*; H9 1*; H10 1*; H11 1*; H12 1*; H17 1*; H18 1*

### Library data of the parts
!PCB1 = CMP-0003618-2: Manufacturer: Any; PartNumber: TIDA-050077
H1-H4 H9-H12 H17 H18 = CMP-0003617-1: Machine Screw, Round, #4-40 x 1/4, Nylon, Philips panhead; Manufacturer: B&F Fastener Supply; CompType: Hardware
H5-H8 H13-H16 H19 H20 = CMP-0003610-1: Standoff, Hex, 0.5"L #4-40 Nylon; Manufacturer: Keystone; CompType: Hardware
L1 = CMP-0074769-1
L2 = CMP-0074847-1: FCC_disclaimer
L3 = CMP-0074837-1: IEC 61010-1 Hot Surface Warning; SymbolCreator: a0412235
L4 = CMP-0074844-1: SymbolCreator: a0412235
Logo1 = CMP-0074838-1: Texas Instrument Corporate Signature; SymbolCreator: a0412235; Lib Reference: TI_Logo; Library Reference: Logo
SH1-SH9 = CMP-0003763-2: Shunt, 2.54mm, Gold, Blue; Manufacturer: Wurth Elektronik
ZZ1 = CMP-0003616-3
ZZ2 = CMP-0077236-1
ZZ3 = CMP-0077237-1
ZZ4 = CMP-0077238-1

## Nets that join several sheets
+3P3V: TIDA-050077_DUT_1 (R43.1 R44.1), TIDA-050077_HKeeping (8 pins)
EN: TIDA-050077_DUT_1 (8 pins), TIDA-050077_DUT_2_3_4 (RZ12.2 RZ19.2 RZ26.2), TIDA-050077_DUT_5_6 (RZ33.2 RZ40.2)
IMON: TIDA-050077_DUT_1 (CM1.2 RZ11.2), TIDA-050077_DUT_2_3_4 (RZ18.2 RZ25.2 RZ32.2), TIDA-050077_DUT_5_6 (RZ39.2 RZ46.2)
IREF: TIDA-050077_DUT_1 (CF1.1 R45.2 TP30.1 U1.9), TIDA-050077_DUT_2_3_4 (U2.9 U3.9 U4.9), TIDA-050077_DUT_5_6 (U5.9 U6.9)
PG: TIDA-050077_DUT_1 (R44.2 RZ10.2), TIDA-050077_DUT_2_3_4 (RZ17.2 RZ24.2 RZ31.2), TIDA-050077_DUT_5_6 (RZ38.2 RZ45.2)
PGND: TIDA-050077_DUT_1 (57 pins), TIDA-050077_DUT_2_3_4 (12 pins), TIDA-050077_DUT_5_6 (8 pins), TIDA-050077_HKeeping (27 pins)
QGND: TIDA-050077_DUT_1 (26 pins), TIDA-050077_DUT_2_3_4 (24 pins), TIDA-050077_DUT_5_6 (16 pins), TIDA-050077_HKeeping (47 pins)
SWEN: TIDA-050077_DUT_1 (R49.1 RZ9.2), TIDA-050077_DUT_2_3_4 (RZ16.2 RZ23.2 RZ30.2), TIDA-050077_DUT_5_6 (RZ37.2 RZ44.2)
TEMP: TIDA-050077_DUT_1 (CTEMP1.1 RZ8.2), TIDA-050077_DUT_2_3_4 (RZ15.2 RZ22.2 RZ29.2), TIDA-050077_DUT_5_6 (RZ36.2 RZ43.2)
VIN: TIDA-050077_DUT_1 (42 pins), TIDA-050077_DUT_2_3_4 (21 pins), TIDA-050077_DUT_5_6 (14 pins), TIDA-050077_HKeeping (C8.1 C15.1 U14.2 U15.2)
VOUT: TIDA-050077_DUT_1 (24 pins), TIDA-050077_DUT_2_3_4 (15 pins), TIDA-050077_DUT_5_6 (10 pins), TIDA-050077_HKeeping (11 pins)
DVDT: TIDA-050077_DUT_1 (5 pins), TIDA-050077_DUT_2_3_4 (RZ14.2 RZ21.2 RZ28.2), TIDA-050077_DUT_5_6 (RZ35.2 RZ42.2)
NetQ1_1: TIDA-050077_DUT_1 (TP17.1), TIDA-050077_HKeeping (Q1.1)
NetQ2_1: TIDA-050077_DUT_1 (TP9.1), TIDA-050077_HKeeping (Q2.1)
NetQ3_1: TIDA-050077_DUT_1 (TP10.1), TIDA-050077_HKeeping (Q3.1 R5.2)
NetQ4_1: TIDA-050077_DUT_1 (TP11.1), TIDA-050077_HKeeping (Q4.1 R6.2)
NetQ5_1: TIDA-050077_DUT_1 (TP12.1), TIDA-050077_HKeeping (Q5.1 R10.2)
NetQ6_1: TIDA-050077_DUT_1 (TP13.1), TIDA-050077_HKeeping (Q6.1 R11.2)
NetQ7_1: TIDA-050077_DUT_1 (TP14.1), TIDA-050077_HKeeping (Q7.1 R12.2)

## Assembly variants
Six-devices: not fitted C4 C5 CO4 CO5 CO6 CO7 R13 R14 R23 R24 R25 R26 R27 R33 R34 R35 R36 R37 R38 R47 R50 R55 R60 R63 R65 R68 R70 R73 R75 R78 R80
Four-devices-all-top: not fitted C4 C5 CO4 CO5 CO6 CO7 R13 R14 R23 R24 R25 R26 R27 R33 R34 R35 R36 R37 R38 R47 R50 R55 R60 R68 R70 R78 R80 RZ19 RZ21 RZ22 RZ23 RZ24 RZ25 RZ33 RZ35 RZ36 RZ37 RZ38 RZ39
Four-devices-top-bottom: not fitted C4 C5 CO4 CO5 CO6 CO7 R13 R14 R23 R24 R25 R26 R27 R33 R34 R35 R36 R37 R38 R47 R50 R63 R65 R68 R70 R73 R75 RZ12 RZ14 RZ15 RZ16 RZ17 RZ18 RZ40 RZ42 RZ43 RZ44 RZ45 RZ46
